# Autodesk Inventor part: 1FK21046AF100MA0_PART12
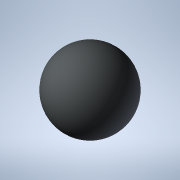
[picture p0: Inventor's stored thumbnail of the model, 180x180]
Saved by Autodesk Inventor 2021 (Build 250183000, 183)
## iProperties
Created: 2025-04
Part Number: 1FK21046AF100MA0_PART12
Material: Generic
Catalog Web Link: www.3dfindit.com
Description: -Servo synchronous motor
Document SubType Name: Modeling
Designer: psAdmin
Mass: 0.137258 g
Surface Area: 1.2868 cm^2
Volume: 0.137258 cm^3
Density: 1 g/cm^3
Appearance: PSOLRGB-212-217-219
Category: PARTsolutions
Title: 1FK21046AF100MA0_PART12
Author: Cadenas PARTsolutions
Comments: Servo synchronous motor
Sending System: PARTsolutions
Preprocessor: ST-DEVELOPER v19.3
PSOL_IDENT_0: {$CADENAS_DATA/23d-libs/siemens_ag/_cat_/4f/2b/1fk21046af100ma0.prj},216 {VTYP=3D},{NB=1FK21046AF100
PSOL_IDENT_1: MA0_PART12},{LINA=1FK21046AF100MA0_PART12},{NN=1FK21046AF100MA0_PART12},{NOPRJ=TRUE},{DATE=19.08.202
PSOL_IDENT_2: 5 14:00:37},{GEOMDATE=30.07.2025 02:01:06},{VERSION=},{LINEID=10},{WBVAR=},{WBNUMERIC=}  {NB=1FK2104
PSOL_IDENT_3: 6AF100MA0_PART12},{LINA=1FK21046AF100MA0_PART12},{KT=DUMMY},{PREVIEW=../../../_pool_/cb/72/p_d211_xx
PSOL_IDENT_4: _00434j.png},{DESCSHORT=SIMOTICS S-1FK2 HD, SINAMICS S210 3AC 400V-480V, 3.2 Nm, 3000 rpm},{DESCLONG=
PSOL_IDENT_5: SIMOTICS S-1FK2 HD servo motor M0=3.2 Nm; PN = 1 kW at nN=3000 rpm (380-480 V); PN = 0.5 kW at nN=15
PSOL_IDENT_6: 00 rpm (200-240 V); with holding brake; degree of protection IP64; cylindrical shaft D19x40mm; absol
PSOL_IDENT_7: ute encoder 22-bit + 12-bit multiturn (encoder AM22DQC); with OCC interface; plug size M17, rotatabl
PSOL_IDENT_8: e; SIMOTICS S-1FK2 servomotorfor a wide range of uses in industrial environments. SIMOTICS S‑1FK2 se
PSOL_IDENT_9: rvomotors are compact synchronous motors with a high dynamic performance that set themselves apart a
PSOL_IDENT_10: s a result of their high power density, degree of protection and overload capability. The motors are
PSOL_IDENT_11: available in two variants: as High Dynamic variant (highest dynamic performance as a result of the
PSOL_IDENT_12: low intrinsic moment of inertia for applications demanding a high dynamic performance with low moved
PSOL_IDENT_13: masses) - and as Compact variant (precise and stable closed-loop control for medium up to large mov
PSOL_IDENT_14: ed masses as a result of a medium intrinsic moment of inertia). SIMOTICSS‑1FK2 servomotors fully exp
PSOL_IDENT_15: loit their strengths in a system with the SINAMICSS210 frequency converter and simple connection usi
PSOL_IDENT_16: ng the one cable connection (OCC). Advantages include the short control and positioning times, fast
PSOL_IDENT_17: and precise correction of disturbing quantities as well as stable control with a high dynamic perfor
PSOL_IDENT_18: mance. The servo motors can be configured to address a wide range of requirements. For example with
PSOL_IDENT_19: and without holding brake, IP64 or IP65 degree of protection, singleturn or multiturn absolute encod
PSOL_IDENT_20: ers - to name just a few. Further, the servomotors are available in different shaft heights extendin
PSOL_IDENT_21: g from 20 to 100. A shaft sealing ring is available to achieve an IP65 degree of protection and for
PSOL_IDENT_22: subsequent mounting at the motor or as spare part. SIMOTICS - the optimum motor for each and every m
PSOL_IDENT_23: otion control application.},{INTNO=195125049673},{SUPPLIERALTNO=1FK2104-6AF10-0MA0},{MANUID=1FK21046
PSOL_IDENT_24: AF100MA0},{MANUNAME=Siemens},{MANUTYPEDESC=Synchronous motor 1FK2-HD 3.2 NM},{AAU732=SIMOTICS},{AAO0
PSOL_IDENT_25: 57=S-1FK2},{AAU734=SIMOTICS S-1FK2 HD servo motor M0=3.2 Nm; PN = 1 kW at nN=3000 rpm (380-480 V); P
PSOL_IDENT_26: N = 0.5 kW at nN=1500 rpm (200-240 V); with holding brake; degree of protection IP64; cylindrical sh
PSOL_IDENT_27: aft D19x40mm; absolute encoder 22-bit + 12-bit multiturn (encoder AM22DQC); with OCC interface; plug
PSOL_IDENT_28: size M17, rotatable;},{AAW338=Synchronous motor 1FK2-HD 3.2 NM},{AAO742=SIMOTICS},{AAO663=404294869
PSOL_IDENT_29: 4534},{NOCUPEROU=1},{PRICEQUANTITY=1},{QUANTITYMIN=1},{QUANTITYINT=1},{CTN=85015220},{COO=DE},{AAO67
PSOL_IDENT_30: 6=1FK2104-6AF10-0MA0},{AAO677=Siemens AG},{ORDERUNIT=C62},{CONTENTUNIT=C62}
NB: 1FK21046AF100MA0_PART12
NT: Servo synchronous motor
NBSYN: $MANUID._PART12
LINA: 1FK21046AF100MA0_PART12
CATALOG: SIEMENS
PREVIEW: ../../../_pool_/cb/72/p_d211_xx_00434j.png
DESCSHORT: SIMOTICS S-1FK2 HD, SINAMICS S210 3AC 400V-480V, 3.2 Nm, 3000 rpm
DESCLONG: SIMOTICS S-1FK2 HD servo motor M0=3.2 Nm; PN = 1 kW at nN=3000 rpm (380-480 V); PN = 0.5 kW at nN=1500 rpm (200-240 V); with holding brake; degree of protection
INTNO: 195125049673
SUPPLIERALTNO: 1FK2104-6AF10-0MA0
MANUID: 1FK21046AF100MA0
MANUNAME: Siemens
MANUTYPEDESC: Synchronous motor 1FK2-HD 3.2 NM
AAU732: SIMOTICS
AAO057: S-1FK2
AAU734: SIMOTICS S-1FK2 HD servo motor M0=3.2 Nm; PN = 1 kW at nN=3000 rpm (380-480 V); PN = 0.5 kW at nN=1500 rpm (200-240 V); with holding brake; degree of protection
AAW338: Synchronous motor 1FK2-HD 3.2 NM
AAO742: SIMOTICS
AAO663: 4042948694534.0
NOCUPEROU: 1
PRICEQUANTITY: 1
QUANTITYMIN: 1
QUANTITYINT: 1
CTN: 85015220
COO: DE
ARTICLENO: 1FK21046AF100MA0_PART12
BOMINFO: 1FK21046AF100MA0_PART12
CREATOR: CADENAS GmbH
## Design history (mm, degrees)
feature "2025_04_17_14_59_39_0177"
body "Solid1"
